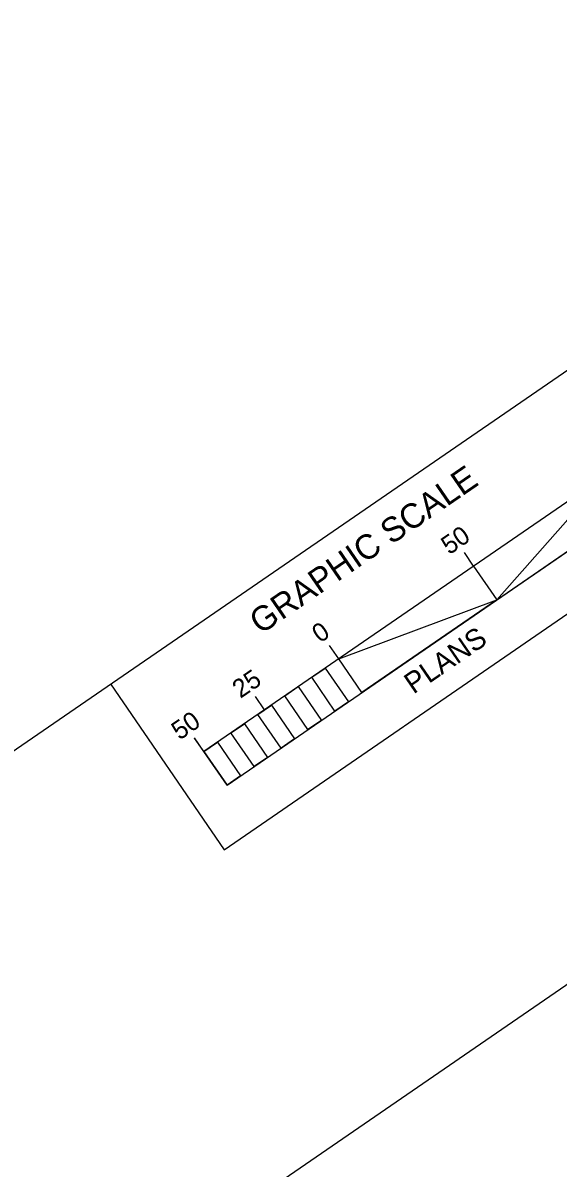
# Model space of a CAD drawing. Extents: x 2385901 to 2398119, y 552503 to 560016.
# Drawn here: x 2397203.6 to 2397367.2, y 559638.4 to 559988.2 of the extents above; entities that cross this region are included whole.
import ezdxf

# ---------------------------------------------------------------- set-up
doc = ezdxf.new("R2010")
doc.units = 0
for name, color, linetype in [('Old_Level_1', 7, 'Continuous'), ('Old_Level_18', 7, 'Continuous'), ('Old_Level_38', 7, 'Continuous'), ('Old_Level_40', 7, 'Continuous'), ('Old_Level_50', 7, 'Continuous')]:
    doc.layers.add(name, color=color, linetype=linetype)

msp = doc.modelspace()

# ---------------------------------------------------------------- linework, layer by layer
at = {"layer": 'Old_Level_1'}
for p, q in [((2397382.56, 559850.56), (2397258.91, 559765.63)), ((2397265.99, 559755.33), (2397389.64, 559840.24)), ((2397341.35, 559822.27), (2397338.52, 559826.38)), ((2397341.34, 559822.25), (2397338.52, 559826.36)), ((2397341.34, 559822.25), (2397348.42, 559811.95)), ((2397300.14, 559793.93), (2397297.3, 559798.05)), ((2397277.47, 559778.36), (2397274.64, 559782.47)), ((2397277.46, 559778.34), (2397274.64, 559782.45)), ((2397277.46, 559778.34), (2397277.46, 559778.34)), ((2397258.92, 559765.65), (2397256.09, 559769.76)), ((2397258.91, 559765.63), (2397256.09, 559769.74)), ((2397258.91, 559765.63), (2397265.99, 559755.33)), ((2397258.91, 559765.63), (2397258.91, 559765.63))]:
    msp.add_line(p, q, dxfattribs=at)
at = {"layer": 'Old_Level_18'}
msp.add_lwpolyline([(2397524.57, 559988.17), (2396288.13, 559138.87), (2396882.63, 558273.38), (2398119.05, 559122.67)], close=True, dxfattribs=at)
at = {"layer": 'Old_Level_38'}
msp.add_line((2397287.76, 559785.45), (2397294.84, 559775.14), dxfattribs=at)
for points in [[(2397382.56, 559850.56), (2397348.42, 559811.95), (2397389.64, 559840.24)], [(2397300.14, 559793.93), (2397348.42, 559811.95), (2397307.21, 559783.63)], [(2397291.89, 559788.28), (2397296.01, 559791.11), (2397303.09, 559780.79), (2397298.96, 559777.97)], [(2397283.65, 559782.61), (2397287.76, 559785.45), (2397294.84, 559775.14), (2397290.72, 559772.31)], [(2397275.41, 559776.94), (2397279.53, 559779.77), (2397286.6, 559769.48), (2397282.48, 559766.65)], [(2397267.16, 559771.29), (2397271.29, 559774.11), (2397278.36, 559763.81), (2397274.25, 559760.99)], [(2397258.91, 559765.63), (2397263.04, 559768.46), (2397270.11, 559758.16), (2397265.99, 559755.33)]]:
    msp.add_lwpolyline(points, close=True, dxfattribs=at)
at = {"layer": 'Old_Level_40'}
for p, q in [((2397265.13, 559735.63), (2397410.83, 559835.71)), ((2397230.37, 559786.24), (2397265.13, 559735.63))]:
    msp.add_line(p, q, dxfattribs=at)
at = {"layer": 'Old_Level_50'}
msp.add_lwpolyline([(2396323.89, 559136.9), (2397107.84, 559675.39), (2397182.92, 559566.09), (2397427.9, 559734.37), (2397466.74, 559677.83), (2397606.19, 559773.62), (2398061.84, 559110.28), (2396893.45, 558307.72)], close=True, dxfattribs=at)

# ---------------------------------------------------------------- texts
at = {"layer": 'Old_Level_1'}
msp.add_text('PLANS', height=6.375, rotation=34.4849, dxfattribs=at).set_placement((2397322.97, 559783))
at = {"layer": 'Old_Level_38'}
for s, height, p in [('50', 5.625, (2397333.9, 559825.55)), ('0', 5.62, (2397294.42, 559798.6)), ('25', 5.625, (2397270.09, 559781.69)), ('50', 5.625, (2397251.47, 559768.93))]:
    msp.add_text(s, height=height, rotation=34.4849, dxfattribs=at).set_placement(p)
at = {"layer": 'Old_Level_40'}
msp.add_text('GRAPHIC SCALE', height=7.4999, rotation=34.4849, dxfattribs=at).set_placement((2397276.22, 559801.19))

doc.saveas('drawing.dxf')
